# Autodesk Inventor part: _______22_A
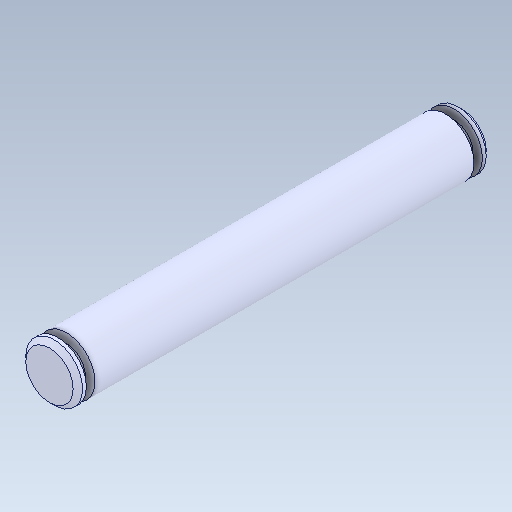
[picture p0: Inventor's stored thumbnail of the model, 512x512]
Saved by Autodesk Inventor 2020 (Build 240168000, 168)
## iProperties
Created: 2017-09
Part Number: _______22_A
Material: Générique
Document SubType Name: Modeling
Designer: bruno
Density: 1 g/cm^3
Appearance: Par défaut
Author: bruno
Sending System: SolidWorks 2016
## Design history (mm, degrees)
feature "Importée1"
node "Solide1"
